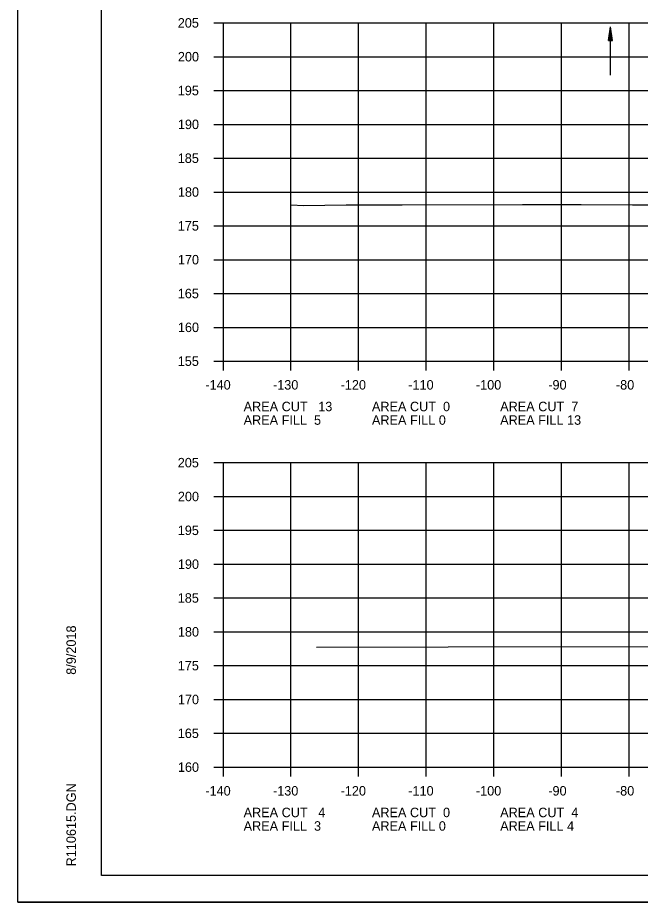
# Model space of a CAD drawing. Extents: x 1372132 to 1372465, y 380083 to 381790.
# Drawn here: x 1372131.6 to 1372223.7, y 380083.5 to 380214.2 of the extents above; entities that cross this region are included whole.
import ezdxf

# ---------------------------------------------------------------- set-up
doc = ezdxf.new("R2010")
doc.units = 0
for name, color, linetype in [('R_Axis', 7, 'Continuous'), ('R_Axis Annot', 7, 'Continuous'), ('R_Border', 7, 'Continuous'), ('R_Dimension', 7, 'Continuous'), ('R_Draft', 7, 'Continuous'), ('R_Exist Surface', 7, 'Continuous'), ('R_Grid', 7, 'Continuous'), ('R_No Plot', 7, 'Continuous')]:
    doc.layers.add(name, color=color, linetype=linetype)

msp = doc.modelspace()

# ---------------------------------------------------------------- linework, layer by layer
at = {"layer": 'R_Axis'}
for p, q in [((1372160.61, 380213.47), (1372162.01, 380213.47)), ((1372162.01, 380163.47), (1372162.01, 380213.47)), ((1372160.61, 380208.47), (1372162.01, 380208.47)), ((1372160.61, 380203.47), (1372162.01, 380203.47)), ((1372160.61, 380198.47), (1372162.01, 380198.47)), ((1372160.61, 380193.47), (1372162.01, 380193.47)), ((1372160.61, 380188.47), (1372162.01, 380188.47)), ((1372160.61, 380183.47), (1372162.01, 380183.47)), ((1372160.61, 380178.47), (1372162.01, 380178.47)), ((1372160.61, 380173.47), (1372162.01, 380173.47)), ((1372160.61, 380168.47), (1372162.01, 380168.47)), ((1372160.61, 380163.47), (1372162.01, 380163.47)), ((1372162.01, 380163.47), (1372442.01, 380163.47)), ((1372162.01, 380162.07), (1372162.01, 380163.47)), ((1372172.01, 380162.07), (1372172.01, 380163.47)), ((1372182.01, 380162.07), (1372182.01, 380163.47)), ((1372192.01, 380162.07), (1372192.01, 380163.47)), ((1372202.01, 380162.07), (1372202.01, 380163.47)), ((1372212.01, 380162.07), (1372212.01, 380163.47)), ((1372222.01, 380162.07), (1372222.01, 380163.47)), ((1372160.61, 380148.47), (1372162.01, 380148.47)), ((1372162.01, 380103.47), (1372162.01, 380148.47)), ((1372160.61, 380143.47), (1372162.01, 380143.47)), ((1372160.61, 380138.47), (1372162.01, 380138.47)), ((1372160.61, 380133.47), (1372162.01, 380133.47)), ((1372160.61, 380128.47), (1372162.01, 380128.47)), ((1372160.61, 380123.47), (1372162.01, 380123.47)), ((1372160.61, 380118.47), (1372162.01, 380118.47)), ((1372160.61, 380113.47), (1372162.01, 380113.47)), ((1372160.61, 380108.47), (1372162.01, 380108.47)), ((1372160.61, 380103.47), (1372162.01, 380103.47)), ((1372162.01, 380103.47), (1372442.01, 380103.47)), ((1372162.01, 380102.07), (1372162.01, 380103.47)), ((1372172.01, 380102.07), (1372172.01, 380103.47)), ((1372182.01, 380102.07), (1372182.01, 380103.47)), ((1372192.01, 380102.07), (1372192.01, 380103.47)), ((1372202.01, 380102.07), (1372202.01, 380103.47)), ((1372212.01, 380102.07), (1372212.01, 380103.47)), ((1372222.01, 380102.07), (1372222.01, 380103.47))]:
    msp.add_line(p, q, dxfattribs=at)
at = {"layer": 'R_Border'}
for p, q in [((1372144.01, 380087.47), (1372144.01, 380292.93)), ((1372144.01, 380087.47), (1372144.01, 380087.47)), ((1372460.19, 380087.47), (1372144.01, 380087.47))]:
    msp.add_line(p, q, dxfattribs=at)
at = {"layer": 'R_Dimension'}
for p, q in [((1372218.95, 380210.87), (1372219.25, 380212.87)), ((1372218.95, 380210.87), (1372219.25, 380212.87)), ((1372219, 380210.87), (1372219.25, 380212.54)), ((1372219, 380210.87), (1372219.25, 380212.54)), ((1372219.05, 380210.87), (1372219.25, 380212.2)), ((1372219.05, 380210.87), (1372219.25, 380212.2)), ((1372219.1, 380210.87), (1372219.25, 380211.86)), ((1372219.1, 380210.87), (1372219.25, 380211.86)), ((1372219.55, 380210.87), (1372219.25, 380212.87)), ((1372219.55, 380210.87), (1372219.25, 380212.87)), ((1372219.5, 380210.87), (1372219.25, 380212.54)), ((1372219.5, 380210.87), (1372219.25, 380212.54)), ((1372219.45, 380210.87), (1372219.25, 380212.2)), ((1372219.45, 380210.87), (1372219.25, 380212.2)), ((1372219.4, 380210.87), (1372219.25, 380211.86)), ((1372219.4, 380210.87), (1372219.25, 380211.86)), ((1372218.95, 380210.87), (1372219.55, 380210.87)), ((1372218.95, 380210.87), (1372219.55, 380210.87)), ((1372219.15, 380210.87), (1372219.25, 380211.52)), ((1372219.15, 380210.87), (1372219.25, 380211.52)), ((1372219.2, 380210.87), (1372219.25, 380211.19)), ((1372219.2, 380210.87), (1372219.25, 380211.19)), ((1372219.35, 380210.87), (1372219.25, 380211.52)), ((1372219.35, 380210.87), (1372219.25, 380211.52)), ((1372219.3, 380210.87), (1372219.25, 380211.19)), ((1372219.3, 380210.87), (1372219.25, 380211.19))]:
    msp.add_line(p, q, dxfattribs=at)
at = {"layer": 'R_Draft'}
msp.add_line((1372219.25, 380205.73), (1372219.25, 380212.87), dxfattribs=at)
at = {"layer": 'R_Exist Surface'}
for points in [[(1372172.06, 380186.56), (1372173.85, 380186.46), (1372180.17, 380186.57), (1372188.44, 380186.58), (1372206.25, 380186.63), (1372214.93, 380186.64), (1372222.51, 380186.6), (1372224.77, 380186.58)], [(1372175.77, 380121.19), (1372195.26, 380121.23), (1372227.21, 380121.29), (1372232.22, 380121.2), (1372246.02, 380120.99), (1372257.87, 380120.28), (1372262.42, 380120.07), (1372263.09, 380119.88), (1372268.91, 380118.77), (1372269.44, 380118.77), (1372273.89, 380118.84), (1372275.21, 380119.11), (1372279.58, 380120.12), (1372285.82, 380122.43), (1372288.07, 380123.3), (1372292.02, 380124.03), (1372292.3, 380124.07), (1372292.99, 380124.09), (1372302.34, 380124.32), (1372303.1, 380124.31), (1372312.29, 380124.13), (1372317.08, 380123.7), (1372317.45, 380123.67), (1372325.71, 380120.28)]]:
    msp.add_lwpolyline(points, dxfattribs=at)
at = {"layer": 'R_Grid'}
for p, q in [((1372162.01, 380213.47), (1372442.01, 380213.47)), ((1372162.01, 380163.47), (1372162.01, 380213.47)), ((1372172.01, 380163.47), (1372172.01, 380213.47)), ((1372182.01, 380163.47), (1372182.01, 380213.47)), ((1372192.01, 380163.47), (1372192.01, 380213.47)), ((1372202.01, 380163.47), (1372202.01, 380213.47)), ((1372212.01, 380163.47), (1372212.01, 380213.47)), ((1372222.01, 380163.47), (1372222.01, 380213.47)), ((1372162.01, 380208.47), (1372442.01, 380208.47)), ((1372162.01, 380203.47), (1372442.01, 380203.47)), ((1372162.01, 380198.47), (1372442.01, 380198.47)), ((1372162.01, 380193.47), (1372442.01, 380193.47)), ((1372162.01, 380188.47), (1372442.01, 380188.47)), ((1372162.01, 380183.47), (1372442.01, 380183.47)), ((1372162.01, 380178.47), (1372442.01, 380178.47)), ((1372162.01, 380173.47), (1372442.01, 380173.47)), ((1372162.01, 380168.47), (1372442.01, 380168.47)), ((1372162.01, 380163.47), (1372442.01, 380163.47)), ((1372162.01, 380148.47), (1372442.01, 380148.47)), ((1372162.01, 380103.47), (1372162.01, 380148.47)), ((1372172.01, 380103.47), (1372172.01, 380148.47)), ((1372182.01, 380103.47), (1372182.01, 380148.47)), ((1372192.01, 380103.47), (1372192.01, 380148.47)), ((1372202.01, 380103.47), (1372202.01, 380148.47)), ((1372212.01, 380103.47), (1372212.01, 380148.47)), ((1372222.01, 380103.47), (1372222.01, 380148.47)), ((1372162.01, 380143.47), (1372442.01, 380143.47)), ((1372162.01, 380138.47), (1372442.01, 380138.47)), ((1372162.01, 380133.47), (1372442.01, 380133.47)), ((1372162.01, 380128.47), (1372442.01, 380128.47)), ((1372162.01, 380123.47), (1372442.01, 380123.47)), ((1372162.01, 380118.47), (1372442.01, 380118.47)), ((1372162.01, 380113.47), (1372442.01, 380113.47)), ((1372162.01, 380108.47), (1372442.01, 380108.47)), ((1372162.01, 380103.47), (1372442.01, 380103.47))]:
    msp.add_line(p, q, dxfattribs=at)
at = {"layer": 'R_No Plot'}
msp.add_line((1372131.61, 380083.49), (1372464.95, 380083.49), dxfattribs=at)
for points in [[(1372131.61, 380296.83), (1372464.95, 380296.83), (1372464.95, 380083.49), (1372131.61, 380083.49)], [(1372377.93, 380292.93), (1372377.93, 380283.05), (1372413.67, 380283.05), (1372413.67, 380280.13), (1372436.87, 380280.13), (1372436.87, 380255.8), (1372460.19, 380255.8), (1372460.19, 380087.47), (1372144.01, 380087.47), (1372144.01, 380292.93)]]:
    msp.add_lwpolyline(points, close=True, dxfattribs=at)

# ---------------------------------------------------------------- texts
at = {"layer": 'R_Axis Annot'}
for s, p in [('205', (1372155.27, 380212.77)), ('200', (1372155.29, 380207.77)), ('195', (1372155.27, 380202.77)), ('190', (1372155.29, 380197.77)), ('185', (1372155.27, 380192.77)), ('180', (1372155.29, 380187.77)), ('175', (1372155.27, 380182.77)), ('170', (1372155.29, 380177.77)), ('165', (1372155.27, 380172.77)), ('160', (1372155.29, 380167.77)), ('155', (1372155.27, 380162.77)), ('-140', (1372159.35, 380159.27)), ('-130', (1372169.35, 380159.27)), ('-120', (1372179.35, 380159.27)), ('-110', (1372189.35, 380159.27)), ('-100', (1372199.35, 380159.27)), ('-90', (1372210.05, 380159.27)), ('-80', (1372220.05, 380159.27)), ('AREA CUT   13', (1372165.01, 380156.07)), ('AREA CUT  0', (1372183.98, 380156.07)), ('AREA CUT  7', (1372202.94, 380156.07)), ('AREA FILL  5', (1372165.01, 380154.07)), ('AREA FILL 0', (1372183.98, 380154.07)), ('AREA FILL 13', (1372202.94, 380154.07)), ('205', (1372155.27, 380147.77)), ('200', (1372155.29, 380142.77)), ('195', (1372155.27, 380137.77)), ('190', (1372155.29, 380132.77)), ('185', (1372155.27, 380127.77)), ('180', (1372155.29, 380122.77)), ('175', (1372155.27, 380117.77)), ('170', (1372155.29, 380112.77)), ('165', (1372155.27, 380107.77)), ('160', (1372155.29, 380102.77)), ('-140', (1372159.35, 380099.27)), ('-130', (1372169.35, 380099.27)), ('-120', (1372179.35, 380099.27)), ('-110', (1372189.35, 380099.27)), ('-100', (1372199.35, 380099.27)), ('-90', (1372210.05, 380099.27)), ('-80', (1372220.05, 380099.27)), ('AREA CUT   4', (1372165.01, 380096.07)), ('AREA CUT  0', (1372183.98, 380096.07)), ('AREA CUT  4', (1372202.94, 380096.07)), ('AREA FILL  3', (1372165.01, 380094.07)), ('AREA FILL 0', (1372183.98, 380094.07)), ('AREA FILL 4', (1372202.94, 380094.07))]:
    msp.add_text(s, height=1.4, dxfattribs=at).set_placement(p)
at = {"layer": 'R_Border'}
for s, p in [('8/9/2018', (1372140.21, 380117.12)), ('R110615.DGN', (1372140.21, 380088.8))]:
    msp.add_text(s, height=1.4, rotation=90, dxfattribs=at).set_placement(p)

doc.saveas('drawing.dxf')
